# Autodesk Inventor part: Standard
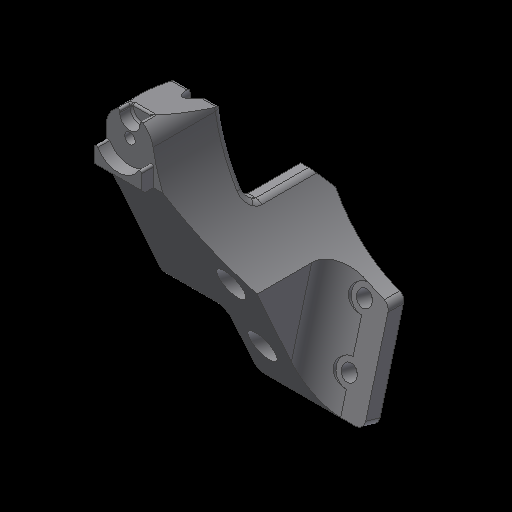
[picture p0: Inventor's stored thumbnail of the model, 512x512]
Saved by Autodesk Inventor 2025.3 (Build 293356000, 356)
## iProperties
RuleStatus: InUse
Created: 2026-05
Project: COMMON
Material: Generic
Catalog Web Link: https://www.janelia.org/
Vendor: HHMI: JRC - JET
Document SubType Name: Modeling
Designer: sohna
Density: 1 g/cm^3
Appearance: Default
AfterDocSave0: file://Part Number Cleaner
LAB/DEPT: COMMON
REQUESTING SCIENTIST: COMMON
DESIGN DEPARTMENT: HHMI: JRC - ID&F
ALTERED ITEM PART NUMBER: N/A
ALTERED ITEM VENDOR: N/A
ALTERED ITEM DESCRIPTION: N/A
Title: Standard
Author: sohna
Revision Number: 0
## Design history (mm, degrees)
sketch "Sketch1"
  geometry: L1 (16.198, -190.69)-(-109.373, -157.043); L2 (-46.587, -173.867)-(0, 0); L3 (0, 301.7)-(0, -301.7) reference; L4 (-301.7, 0)-(301.7, 0) reference; L5 (-2.7, -113.9)-(-22.7, -113.9); L6 (-22.7, -113.9)-(-22.7, -88.9); L7 (-22.7, -88.9)-(-2.7, -88.9); L8 (-2.7, -88.9)-(-2.7, -113.9); L9 (-2.7, -113.9)-(-25.875, -113.9); L10 (-25.875, -113.9)-(-107.729, -150.91); L11 (-107.729, -150.91)-(-109.373, -157.043); L12 (-109.373, -157.043)-(-20.632, -180.822); L13 (-20.632, -180.822)-(-2.7, -113.9); L14 (-107.729, -150.91)-(-59.433, -163.851); L15 (-59.433, -163.851)-(-25.875, -113.9); C1 r 215.5 at (0, 0); 2 further points
  constraints: 26 end point, 4 perpendicular, 3 parallel, 3 point on line, 2 horizontal, 2 midpoint, 1 centre point, 1 coincident
  dimensions: "d0" = 431 diameter of C1; "d1" = 130 distance of L1.start L1.end; "d2" = 180 distance of L2.start L2.end; "d3" = 15 deg angle of L3 L2; "d4" = 20 distance of L6.end L7.end; "d5" = 25 distance of L7.end L5.start; "d6" = 88.9 distance between parallel lines of L7 L4; "d7" = 12.7 distance from line of L3 point (-12.7, -88.9); "d9" = 6.35 distance of L10.end L11.end; "d10" = 3.175 distance from line of L9.end L6; "d13" = 50 distance from line of L11 L14.end
extrude "Extrusion1" new body sketch "Sketch1" distance "d11" = 72.39; taper "d12" = 0 deg
sketch "Sketch3"
  geometry: L1 (-113.9, -2.7)-(-180.822, -20.632) reference; L2 (-143.51, -10.634)-(-143.51, -159.88); L3 (-157.043, -109.373)-(-180.822, -20.632) reference; L4 (-113.9, -25.875)-(-113.9, -2.7) reference; L5 (-150.91, -107.729)-(-113.9, -25.875) reference; L6 (-157.043, -109.373)-(-150.91, -107.729) reference; L7 (-180.822, -20.632)-(-157.043, -109.373) reference; 3 further points
  constraints: 2 end point, 2 point on line, 1 parallel
  dimensions: "d86" = 143.51 distance from line of point (0, 0) L2
extrude "Extrusion3" cut sketch "Sketch3" distance "d28" = 27.39; taper "d29" = 0 deg
workplane "Work Plane1"
sketch "Sketch4"
  geometry: L1 (35, -51.871)-(10, -51.871); L2 (10, -51.871)-(10, -76.871); L3 (10, -76.871)-(35, -76.871); L4 (35, -76.871)-(35, -51.871); L5 (0, -91.871)-(45, -91.871) reference; L6 (0, -91.871)-(0, 0) reference; 5 further points
  constraints: 8 end point, 4 coincident, 2 parallel, 2 perpendicular, 1 horizontal
  dimensions: "d31" = 25 distance of L1.end L2.end; "d32" = 15 distance between parallel lines of L5 L3; "d33" = 10 distance between parallel lines of L6 L2
hole "Hole2" sketch "Sketch4" at (35, -51.871), (10, -51.871), (10, -76.871), (35, -76.871) diameter "d34" = 6.604; stored, may be unused: countersink angle "d38" = 90 deg, drill point angle "d40" = 118 deg; dims "d35" = 19.05, "d36" = 10.9982, "d37" = 0, "d39" = 25.4
sketch "Sketch5"
  geometry: L1 (-180.822, -20.632)-(-143.51, -10.634) reference; L2 (-157.043, -109.373)-(-180.822, -20.632) reference; L3 (-150.91, -107.729)-(-157.043, -109.373) reference; L4 (-143.51, -40.64)-(-175.46, -40.64); L5 (-216.986, 0)-(36.164, 0) reference; L6 (0, 21.875)-(0, -131.247) reference; L7 (-143.51, -91.363)-(-150.91, -107.729) reference; L8 (-143.51, -10.634)-(-143.51, -91.363) reference; 1 further point
  constraints: 2 end point, 2 point on line, 1 horizontal
  dimensions: "d41" = 40.64 distance between parallel lines of L4 L5
extrude "Extrusion4" cut sketch "Sketch5" extent not by distance; stored distance "d42" = 0; taper "d43" = 0 deg
sketch "Sketch6" dims "d56" = 20
  geometry: L1 (0, 134.374)-(0, -119.81) reference; L2 (-108.877, 25.875)-(119.865, 25.875) reference; L3 (0, 23.175)-(-72.39, 23.175) reference; L4 (0, 23.175)-(0, 0) reference; L5 (0, 0)-(0, -81.854) reference; L6 (-72.39, 0)-(-72.39, 23.175) reference; L7 (-52.39, 13.175)-(-52.39, 0); L8 (-52.39, 0)-(-72.39, 0); C1 r 68.425 at (15, 25.875); 7 further points
  constraints: 4 end point, 3 vertical, 2 horizontal, 1 centre point, 1 coincident, 1 point on line, 4 other
  dimensions: "d44" = 15 distance from line of point (15, 25.875) L1
extrude "Extrusion5" cut sketch "Sketch6" extent not by distance; stored distance "d46" = 0; taper "d47" = 0 deg
sketch "Sketch8"
  geometry: L1 (45, 6.35)-(0, 6.35) reference; L2 (45, 34.846)-(45, 6.35) reference; L3 (45, 6.35)-(22.5, 6.35); L4 (22.5, 6.35)-(22.5, 121.091); L5 (22.5, 121.091)-(45, 121.091); L6 (45, 121.091)-(45, 6.35); A1 r 12.7 centre (35.2, 19.05) between (22.5, 19.05) and (35.2, 6.35); 8 further points; 1 other entity
  constraints: 8 end point, 2 parallel, 2 point on circle, 2 point on line, 2 tangent, 1 centre point, 1 horizontal, 1 perpendicular, 2 other
  dimensions: "d51" = 22.5 distance between parallel lines of L2 L4; "d54" = 12.7 radius of A1
extrude "Extrusion7" cut sketch "Sketch8" extent not by distance; stored distance "d52" = 0; taper "d53" = 0 deg
extrude "Extrusion8" cut sketch "Sketch6" extent not by distance; stored distance "d57" = 0; taper "d58" = 0 deg
extrude "Extrusion9" join sketch "Sketch6" distance "d59" = 5.08; taper "d60" = 0 deg
fillet "Fillet1" dims "d61" = 0.762
chamfer "Chamfer1" distance "d62" = 1.524; stored, may be unused: second distance "d63" = 3.175, angle "d64" = 45 deg
chamfer "Chamfer2" distance "d66" = 6.35; stored, may be unused: second distance "d67" = 3.175, angle "d68" = 45 deg
fillet "Fillet2" dims "d65" = 3.175
workplane "Work Plane2"
sketch "Sketch10"
  geometry: L1 (0, 7.654)-(0, 0) reference; L2 (4.046, 0)-(0, 0) reference; L3 (-20, 13.175)-(-20, 7.654) reference; A1 r 10 centre (-10, 13.175) between (-18.584, 8.045) and (-1.416, 8.045) reference; A2 r 0.762 centre (-0.762, 7.654) between (0, 7.654) and (-1.416, 8.045) reference; A3 r 68.425 centre (67.39, 25.875) between (-0.132, 14.794) and (4.046, 0) reference; A4 r 10 centre (-10, 13.175) between (-0.132, 14.794) and (-10, 23.175) reference; A5 r 10 centre (-10, 13.175) between (-10, 23.175) and (-20, 13.175) reference; A6 r 0.762 centre (-19.238, 7.654) between (-18.584, 8.045) and (-20, 7.654) reference; 2 further points
  constraints: 1 coincident
hole "Hole3" sketch "Sketch10" at (-10, 13.175) diameter "d70" = 4.4958; stored, may be unused: countersink angle "d74" = 82 deg, drill point angle "d76" = 118 deg; dims "d71" = 19.05, "d72" = 8.001, "d73" = 0, "d75" = 25.4
sketch "Sketch11"
  geometry: L1 (0, 7.654)-(0, 0) reference; L2 (4.046, 0)-(0, 0) reference; L3 (-20, 13.175)-(-20, 7.654) reference; L4 (-14.318, 20.381)-(-14.318, 22.195); L5 (-5.682, 20.381)-(-5.682, 22.195); L6 (-10, 20.381)-(-10, 13.175); L7 (-11.905, 20.381)-(-11.905, 22.992); L8 (-8.095, 20.381)-(-8.095, 22.992); C1 r 2.248 at (-10, 13.175) reference; A1 r 10 centre (-10, 13.175) between (-18.584, 8.045) and (-1.416, 8.045) reference; A2 r 0.762 centre (-0.762, 7.654) between (0, 7.654) and (-1.416, 8.045) reference; A3 r 68.425 centre (67.39, 25.875) between (-0.132, 14.794) and (4.046, 0) reference; A4 r 10 centre (-10, 13.175) between (-0.132, 14.794) and (-10, 23.175) reference; A5 r 10 centre (-10, 13.175) between (-10, 23.175) and (-20, 13.175) reference; A6 r 0.762 centre (-19.238, 7.654) between (-18.584, 8.045) and (-20, 7.654) reference; A7 r 4.318 centre (-10, 20.381) between (-14.318, 20.381) and (-5.682, 20.381); A8 r 1.905 centre (-10, 20.381) between (-11.905, 20.381) and (-8.095, 20.381); 2 further points
  constraints: 10 end point, 9 point on circle, 4 tangent, 4 vertical, 2 centre point, 1 point on line, 1 other
  dimensions: "d77" = 7.112 distance of point (-10, 16.063) A4.end; "d78" = 8.636 distance between parallel lines of L5 L4; "d81" = 3.81 diameter of A8
  node "Projected Loop4"
extrude "Extrusion10" cut sketch "Sketch11" distance "d79" = 5.08; taper "d80" = 0 deg
extrude "Extrusion11" cut sketch "Sketch11" extent not by distance; stored distance "d83" = 0; taper "d84" = 0 deg
fillet "Fillet3" dims "d85" = 0.762
fillet "Fillet4" dims "d87" = 3.175
body "Solid1"
node "Projected Loop2"
node "Projected Loop3"
other parameters: "d30" = -6.35, "d69" = -6.35
